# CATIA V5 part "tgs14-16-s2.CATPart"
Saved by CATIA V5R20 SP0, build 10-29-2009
Part number: TGS14-16-S2
Revision: 1
Definition: design
Nomenclature: TGS14-16-S2
Source: made
Description: NOT SPECIFIED
Bounding box of the stored display mesh (mm): x -22 to 0.8, y 0 to 14, z -6 to 6
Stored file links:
  C:\Users\Raffaele\Desktop\3D X SITO CF\I-MOLD\TGS-S2\tgs14-s2.step\tgs14-16-s2.CATPart
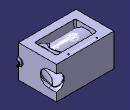
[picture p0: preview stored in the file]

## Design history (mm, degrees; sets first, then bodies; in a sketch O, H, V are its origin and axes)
Set1
  Line1 "LINE #4086": stored without definition
  DatumCurve1 "COMPOSITE_CURVE #4139"
  DatumCurve2 "COMPOSITE_CURVE #4190"
  DatumCurve3 "COMPOSITE_CURVE #4269"
  DatumCurve4 "COMPOSITE_CURVE #4312"
  DatumCurve5 "COMPOSITE_CURVE #4541"
  DatumCurve6 "COMPOSITE_CURVE #4682"
  DatumCurve7 "COMPOSITE_CURVE #4709"
  DatumCurve8 "COMPOSITE_CURVE #4767"
  DatumCurve9 "COMPOSITE_CURVE #4822"
  DatumCurve10 "COMPOSITE_CURVE #4851"
  DatumSurface1 "OPEN_SHELL #4076"
Body1 "MANIFOLD_SOLID_BREP #4077" (main body)
  Solid1: solid without history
